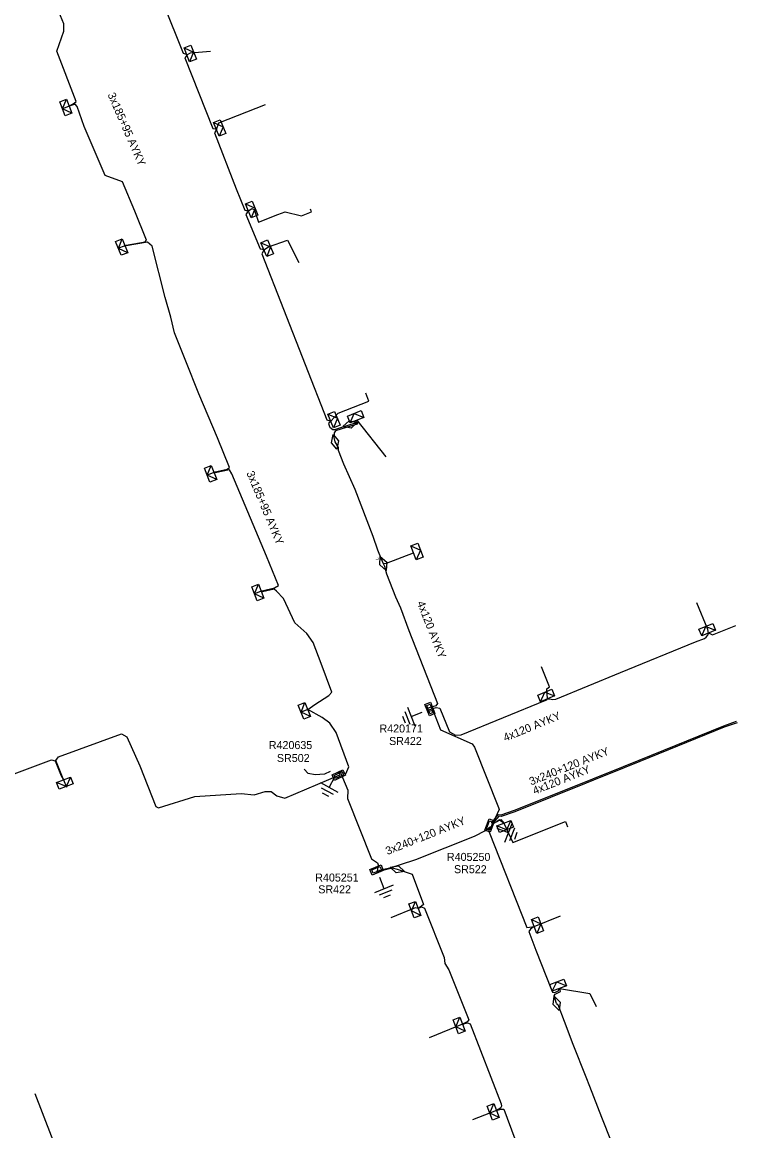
# Model space of a CAD drawing. Extents: x -540028 to -538776, y -1157064 to -1155670.
# Drawn here: x -539821.3 to -539732.2, y -1156179 to -1156040.4 of the extents above; entities that cross this region are included whole.
import ezdxf

# ---------------------------------------------------------------- set-up
doc = ezdxf.new("R2010")
doc.units = 0
for name, color, linetype in [('Vrstva 15', 7, 'Continuous'), ('Vrstva 19', 7, 'Continuous'), ('Vrstva 2', 7, 'Continuous'), ('Vrstva 28', 7, 'Continuous'), ('Vrstva 29', 7, 'Continuous'), ('Vrstva 30', 7, 'Continuous'), ('Vrstva 31', 7, 'Continuous'), ('Vrstva 5', 7, 'Continuous'), ('Vrstva 52', 7, 'Continuous'), ('Vrstva 59', 7, 'Continuous'), ('Vrstva 6', 7, 'Continuous')]:
    doc.layers.add(name, color=color, linetype=linetype)

# ---------------------------------------------------------------- blocks, each defined once
blk = doc.blocks.new('17')
at = {"layer": 'Vrstva 2'}
blk.add_lwpolyline([(-1.875, 0), (0, 0.9375), (1.875, 0), (0, -0.9375)], close=True, dxfattribs=at)
blk = doc.blocks.new('17.1')
at = {"layer": 'Vrstva 2'}
blk.add_lwpolyline([(-1.875, 0), (0, 0.9375), (1.875, 0), (0, -0.9375)], close=True, dxfattribs=at)
blk.add_text('T', height=0.75, dxfattribs=at).set_placement((-1.875, -1.35))
blk = doc.blocks.new('132')
at = {"layer": 'Vrstva 2'}
for points in [[(-1.5, 1.5), (1.5, 1.5), (1.5, 0), (-1.5, 0)], [(-1.1, 1.2), (1.1, 1.2), (1.1, 0.3), (-1.1, 0.3)]]:
    blk.add_lwpolyline(points, close=True, dxfattribs=at)
blk = doc.blocks.new('23')
at = {"layer": 'Vrstva 2'}
blk.add_lwpolyline([(1.875, -1.8), (-1.875, -1.8), (-1.875, 0), (1.875, 0)], close=True, dxfattribs=at)
blk.add_lwpolyline([(1.875, 0), (0, -1.8), (-1.875, 0)], dxfattribs=at)
blk = doc.blocks.new('11')
at = {"layer": 'Vrstva 2'}
for p, q in [((0, -4.3), (0, -1.3)), ((-2.5, -4.3), (2.5, -4.3)), ((-1.7, -5.3), (1.7, -5.3)), ((-0.9, -6.3), (0.9, -6.3))]:
    blk.add_line(p, q, dxfattribs=at)

msp = doc.modelspace()

# ---------------------------------------------------------------- linework, layer by layer
at = {"layer": 'Vrstva 5'}
for points in [[(-539781.35, -1156133.95), (-539781.26, -1156134.18), (-539780.81, -1156134.36), (-539780.46, -1156133.5), (-539782.03, -1156129.18), (-539782.81, -1156128.05), (-539783.79, -1156127.33), (-539785.58, -1156126.33), (-539784.69, -1156125.68), (-539782.94, -1156124.58), (-539782.58, -1156124.14), (-539783.91, -1156120.57), (-539784.89, -1156117.95), (-539785.71, -1156116.83), (-539787.18, -1156115.5), (-539788.62, -1156112.44), (-539789.5, -1156111.52), (-539789.77, -1156111.29), (-539791.22, -1156111.6), (-539791.41, -1156111.55), (-539791.28, -1156111.48), (-539789.71, -1156111.1), (-539789.24, -1156110.84), (-539790.75, -1156107.16), (-539795.07, -1156096.86), (-539795.36, -1156096.36), (-539797.14, -1156096.73), (-539797.3, -1156096.71), (-539797.16, -1156096.63), (-539795.66, -1156096.29), (-539795.36, -1156096.06), (-539796.86, -1156092.37), (-539799.2, -1156086.86), (-539800.81, -1156082.77), (-539802.21, -1156079.24), (-539802.67, -1156077.28), (-539803.41, -1156074.82), (-539805, -1156068.43), (-539805.6, -1156067.92), (-539808.26, -1156068.38), (-539808.41, -1156068.36), (-539808.27, -1156068.29), (-539805.91, -1156067.88), (-539805.72, -1156067.66), (-539807.17, -1156064.05), (-539808.72, -1156060.39), (-539810.88, -1156059.57), (-539813.54, -1156053.46), (-539814.41, -1156050.96), (-539814.63, -1156050.66), (-539815.25, -1156050.89), (-539815.39, -1156050.93), (-539815.27, -1156050.84), (-539814.76, -1156050.56), (-539814.54, -1156050.32), (-539816.94, -1156044.04), (-539816.06, -1156041.53), (-539816.06, -1156040.62), (-539818.34, -1156035.09)], [(-539803.6, -1156038.19), (-539801.16, -1156044.31), (-539800.79, -1156044.42), (-539800.68, -1156044.5), (-539800.72, -1156044.61), (-539800.94, -1156044.86), (-539797.44, -1156053.71), (-539797.13, -1156053.75), (-539797, -1156053.82), (-539797.03, -1156053.94), (-539797.24, -1156054.27), (-539794.53, -1156061.27), (-539793.43, -1156063.91), (-539793.24, -1156063.97), (-539793.11, -1156063.96), (-539792.99, -1156064.01), (-539793.01, -1156064.13), (-539793.14, -1156064.21), (-539793.32, -1156064.47), (-539791.53, -1156068.76), (-539791.2, -1156068.8), (-539791.07, -1156068.86), (-539791.09, -1156069), (-539791.3, -1156069.39), (-539783.2, -1156090.13), (-539782.94, -1156090.2), (-539782.82, -1156090.22), (-539782.71, -1156090.27), (-539782.74, -1156090.39), (-539782.9, -1156090.47), (-539783, -1156090.58), (-539782.85, -1156090.95), (-539782.82, -1156091.04), (-539782.44, -1156091.32), (-539782.2, -1156091.34), (-539780.29, -1156090.7)], [(-539780.29, -1156090.7), (-539779.56, -1156090.51), (-539779.52, -1156090.36), (-539779.42, -1156090.16), (-539779.31, -1156090.35), (-539779.4, -1156090.67), (-539780.23, -1156090.9), (-539782.09, -1156091.51), (-539782.29, -1156091.73), (-539782.31, -1156092.35), (-539782.17, -1156092.87)], [(-539782.17, -1156092.87), (-539781.78, -1156093.6), (-539781.78, -1156093.9), (-539781.11, -1156095.64), (-539779.67, -1156098.77), (-539777.43, -1156104.66), (-539776.87, -1156106.38), (-539776.39, -1156107.5), (-539776.14, -1156108.08)], [(-539776.14, -1156108.08), (-539775.99, -1156108.41), (-539775.75, -1156109.39), (-539774.61, -1156112.26), (-539773.97, -1156113.62), (-539772.96, -1156116.47), (-539769.37, -1156125.56), (-539769.57, -1156125.88), (-539770.7, -1156126.2)], [(-539770.62, -1156126.39), (-539769.51, -1156126.07), (-539769.08, -1156126.14), (-539767.84, -1156129.1), (-539767.11, -1156129.53), (-539766.39, -1156129.49), (-539755.82, -1156125.16), (-539755.7, -1156125.09), (-539755.6, -1156124.99), (-539755.38, -1156124.99), (-539754.95, -1156125.07), (-539754.56, -1156125.03), (-539746.48, -1156121.71), (-539737.12, -1156117.87), (-539735.98, -1156117.45), (-539735.78, -1156117.27), (-539735.59, -1156117.05), (-539735.54, -1156116.89), (-539735.47, -1156116.77), (-539735.34, -1156116.81), (-539734.99, -1156117.01), (-539732.06, -1156115.83)], [(-539770.55, -1156126.58), (-539770.09, -1156126.45), (-539769.85, -1156126.63), (-539768.97, -1156128.88), (-539765.04, -1156130.6), (-539764.75, -1156131.02), (-539761.72, -1156138.58), (-539761.66, -1156138.82), (-539762.15, -1156139.9), (-539762.49, -1156140.54), (-539762.46, -1156140.82), (-539762.44, -1156140.82)], [(-539762.42, -1156140.77), (-539762.58, -1156140.51), (-539761.77, -1156139.43), (-539761.41, -1156139.48), (-539759.74, -1156138.92), (-539750.84, -1156135.37), (-539749.03, -1156134.6), (-539748.05, -1156134.22), (-539744.15, -1156132.65), (-539733.59, -1156128.36), (-539731.98, -1156127.8)], [(-539731.92, -1156127.98), (-539733.53, -1156128.54), (-539744.07, -1156132.83), (-539747.97, -1156134.4), (-539748.95, -1156134.78), (-539750.76, -1156135.55), (-539759.68, -1156139.1), (-539761.39, -1156139.68), (-539761.69, -1156139.65), (-539762.44, -1156140.55), (-539762.39, -1156140.69)], [(-539825.3, -1156135.47), (-539817.59, -1156132.61), (-539817.16, -1156132.74), (-539816.41, -1156134.62), (-539816.11, -1156135.12), (-539816.31, -1156134.58), (-539817.07, -1156132.7), (-539816.73, -1156132.24), (-539808.85, -1156129.36), (-539808.2, -1156129.73), (-539806.58, -1156133.36), (-539804.55, -1156138.43), (-539804.22, -1156138.63), (-539799.69, -1156137.19), (-539793.91, -1156136.82), (-539792.27, -1156137), (-539790.9, -1156136.57), (-539790.16, -1156136.57), (-539789.43, -1156137.13), (-539788.43, -1156137.39), (-539781.58, -1156134.51), (-539781.74, -1156134.13)], [(-539781.55, -1156134.04), (-539780.56, -1156136.39), (-539780.62, -1156137.44), (-539777.61, -1156144.98), (-539776.86, -1156145.49), (-539776.76, -1156145.72), (-539776.93, -1156146.77)], [(-539762.45, -1156140.67), (-539762.94, -1156141.33), (-539762.91, -1156141.64), (-539758.18, -1156153.55), (-539757.85, -1156153.51), (-539757.29, -1156153.43), (-539757.72, -1156153.77), (-539757.93, -1156154.05), (-539757.05, -1156156.4), (-539755.72, -1156159.78), (-539755.19, -1156161.16), (-539754.98, -1156161.64), (-539754.69, -1156161.7), (-539754.2, -1156161.46), (-539754.21, -1156161.32), (-539754.13, -1156161.2)], [(-539762.48, -1156140.92), (-539762.5, -1156140.91), (-539762.45, -1156140.67)], [(-539762.45, -1156140.67), (-539762.42, -1156140.55), (-539761.92, -1156140.31)], [(-539761.92, -1156140.31), (-539762.37, -1156140.57), (-539762.45, -1156140.67)], [(-539761.59, -1156140.15), (-539761.61, -1156140.12), (-539761.92, -1156140.31)], [(-539761.92, -1156140.31), (-539761.59, -1156140.15)], [(-539761.59, -1156140.15), (-539761.45, -1156140.08), (-539761.07, -1156140.52), (-539761.59, -1156140.15)], [(-539776.83, -1156146.73), (-539776.57, -1156146.4), (-539775.01, -1156146.02), (-539773.98, -1156145.7), (-539772.06, -1156145.08), (-539764.72, -1156142.16), (-539763.35, -1156141.46), (-539762.79, -1156140.97), (-539762.51, -1156141.01)], [(-539776.68, -1156146.66), (-539776.54, -1156146.49), (-539775.02, -1156146.11), (-539774.39, -1156146.3)], [(-539774.39, -1156146.3), (-539772.51, -1156146.91), (-539771.12, -1156150.69), (-539771.36, -1156150.91), (-539771.78, -1156151.18), (-539771.34, -1156151), (-539770.97, -1156151.14), (-539768.51, -1156157.33), (-539768.45, -1156158.08), (-539767.94, -1156158.86), (-539765.43, -1156165.12), (-539765.64, -1156165.36), (-539766.23, -1156165.65), (-539765.6, -1156165.48), (-539765.28, -1156165.61), (-539761.4, -1156175.59), (-539761.34, -1156175.91), (-539761.47, -1156176.17), (-539761.97, -1156176.44), (-539761.43, -1156176.28), (-539761.06, -1156176.27), (-539759.68, -1156179.97)], [(-539754.47, -1156163.05), (-539754.79, -1156162.1), (-539754.65, -1156161.9), (-539753.98, -1156161.58), (-539754.02, -1156161.3), (-539754.13, -1156161.2)], [(-539754.47, -1156163.05), (-539754.32, -1156163.21), (-539753.53, -1156165.27), (-539752.45, -1156168.17), (-539750.8, -1156172.24), (-539750.34, -1156173.42), (-539748.88, -1156177.28), (-539747.67, -1156180.3), (-539747.55, -1156180.35), (-539747.29, -1156180.99)]]:
    msp.add_lwpolyline(points, dxfattribs=at)
at = {"layer": 'Vrstva 52'}
for points in [[(-539800.68, -1156044.5), (-539800.22, -1156044.27), (-539797.75, -1156044.03)], [(-539797, -1156053.82), (-539796.68, -1156053.02), (-539790.86, -1156050.71)], [(-539792.99, -1156064.01), (-539792.55, -1156063.72), (-539792.26, -1156063.84), (-539791.72, -1156065.42), (-539789.33, -1156064.48), (-539788.38, -1156064.14), (-539786.35, -1156064.63), (-539785.09, -1156064.14), (-539785.22, -1156063.81)], [(-539791.07, -1156068.86), (-539790.46, -1156068.52), (-539788.11, -1156067.68), (-539786.69, -1156070.45)], [(-539782.71, -1156090.27), (-539781.78, -1156089.28), (-539777.96, -1156087.78), (-539778.32, -1156086.81)], [(-539776.14, -1156108.08), (-539775.75, -1156108.03), (-539772.34, -1156106.75)], [(-539735.47, -1156116.77), (-539735.57, -1156116.33), (-539736.93, -1156112.99)], [(-539755.6, -1156124.99), (-539755.69, -1156123.75), (-539755.37, -1156123.51), (-539756.36, -1156121)], [(-539782.76, -1156134.07), (-539783.5, -1156134.4), (-539784.65, -1156134.49), (-539785.52, -1156134.33), (-539786.02, -1156133.77)], [(-539761.07, -1156140.52), (-539759.94, -1156142.95), (-539753.36, -1156140.34), (-539753.11, -1156140.98)], [(-539771.78, -1156151.18), (-539772.13, -1156151.13), (-539775.21, -1156152.37)], [(-539757.29, -1156153.43), (-539753.99, -1156152.13)], [(-539754.13, -1156161.2), (-539750.33, -1156161.83), (-539749.52, -1156163.45)], [(-539766.23, -1156165.65), (-539770.41, -1156167.37)], [(-539761.97, -1156176.44), (-539764.97, -1156177.61)]]:
    msp.add_lwpolyline(points, dxfattribs=at)
at = {"layer": 'Vrstva 59'}
for points in [[(-539815.39, -1156050.93), (-539816.32, -1156051.29)], [(-539808.41, -1156068.36), (-539809.34, -1156068.72)], [(-539779.42, -1156090.16), (-539775.8, -1156094.75)], [(-539797.3, -1156096.71), (-539798.23, -1156097.08)], [(-539791.41, -1156111.55), (-539792.33, -1156111.92)], [(-539785.58, -1156126.33), (-539786.51, -1156126.69)], [(-539816.11, -1156135.12), (-539815.74, -1156136.05)], [(-539801.29, -1156221.99), (-539819.63, -1156174.34)]]:
    msp.add_lwpolyline(points, dxfattribs=at)

# ---------------------------------------------------------------- block references
at = {"layer": 'Vrstva 15'}
for p, xscale, yscale, rotation in [((-539770.65, -1156126.4), 0.5, 0.5, -68.34053606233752), ((-539781.86, -1156134.19), 0.5000000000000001, 0.5, -28.96766117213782), ((-539762.49, -1156140.96), 0.49999999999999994, 0.5000000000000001, 68.96248884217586), ((-539776.83, -1156146.73), 0.5, 0.5, 22.14718609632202)]:
    msp.add_blockref('11', p, dxfattribs=dict(at, xscale=xscale, yscale=yscale, rotation=rotation))
at = {"layer": 'Vrstva 19', "yscale": 0.5}
for name, p, xscale, rotation in [('17', (-539780.29, -1156090.7), 0.5, 15.068488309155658), ('17', (-539782.17, -1156092.87), 0.49999999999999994, 105.06848819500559), ('17.1', (-539776.14, -1156108.08), 0.49999999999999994, -66.71813605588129), ('17', (-539774.39, -1156146.3), 0.5, -17.976591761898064), ('17', (-539754.47, -1156163.05), 0.49999999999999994, -71.38430834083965)]:
    msp.add_blockref(name, p, dxfattribs=dict(at, xscale=xscale, rotation=rotation))
at = {"layer": 'Vrstva 28'}
for p, xscale, yscale, rotation in [((-539770.65, -1156126.4), 0.5, 0.5, -68.52761672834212), ((-539781.86, -1156134.19), 0.5000000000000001, 0.5000000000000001, -154.7446638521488), ((-539762.49, -1156140.96), 0.49999999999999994, 0.5000000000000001, 68.96248884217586), ((-539776.83, -1156146.73), 0.5, 0.5, 22.14718609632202)]:
    msp.add_blockref('132', p, dxfattribs=dict(at, xscale=xscale, yscale=yscale, rotation=rotation))
at = {"layer": 'Vrstva 31'}
for p, xscale, yscale, rotation in [((-539800.68, -1156044.49), 0.5, 0.5000000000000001, 111.57325831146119), ((-539815.39, -1156050.92), 0.49999999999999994, 0.5, -68.4450194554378), ((-539796.99, -1156053.82), 0.5, 0.5, 111.77743053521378), ((-539792.99, -1156064.01), 0.5, 0.5000000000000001, 112.09416940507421), ((-539808.41, -1156068.36), 0.5, 0.5000000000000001, -68.44328604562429), ((-539791.07, -1156068.86), 0.5, 0.5, 112.95805287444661), ((-539782.71, -1156090.27), 0.5, 0.5, 111.83802224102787), ((-539779.42, -1156090.16), 0.49999999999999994, 0.5000000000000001, -158.16356870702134), ((-539797.3, -1156096.71), 0.49999999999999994, 0.5000000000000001, -68.4762361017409), ((-539772.34, -1156106.75), 0.5, 0.5, 110.97780271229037), ((-539791.4, -1156111.55), 0.5, 0.5, -68.38622222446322), ((-539735.47, -1156116.77), 0.5, 0.5, -157.49231676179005), ((-539755.6, -1156124.99), 0.49999999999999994, 0.5000000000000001, -157.63060270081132), ((-539785.58, -1156126.33), 0.5000000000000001, 0.5, -68.63264170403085), ((-539816.11, -1156135.12), 0.5000000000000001, 0.4999999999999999, 21.592372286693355), ((-539761.07, -1156140.52), 0.5, 0.5, 21.037511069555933), ((-539771.78, -1156151.18), 0.49999999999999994, 0.5000000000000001, -68.96248890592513), ((-539757.29, -1156153.43), 0.5, 0.5000000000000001, 111.03751110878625), ((-539754.13, -1156161.2), 0.5, 0.5, -159.9129499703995), ((-539766.23, -1156165.65), 0.49999999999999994, 0.5000000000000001, -68.96248889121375), ((-539761.97, -1156176.44), 0.49999999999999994, 0.5000000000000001, -68.96248884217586)]:
    msp.add_blockref('23', p, dxfattribs=dict(at, xscale=xscale, yscale=yscale, rotation=rotation))

# ---------------------------------------------------------------- texts
at = {"layer": 'Vrstva 29'}
for s, rotation, p in [('R420171', 0.048, (-539776.61, -1156129.2)), ('R420635', 0.005, (-539790.44, -1156131.27)), ('R405250', 359.852, (-539768.18, -1156145.24)), ('R405251', 0.081, (-539784.64, -1156147.83))]:
    msp.add_text(s, height=1, rotation=rotation, dxfattribs=at).set_placement(p)
at = {"layer": 'Vrstva 30'}
for s, rotation, p in [('SR422', 0.083, (-539775.41, -1156130.76)), ('SR502', 0.003, (-539789.43, -1156132.89)), ('SR522', 359.852, (-539767.3, -1156146.78)), ('SR422', 0.037, (-539784.26, -1156149.3))]:
    msp.add_text(s, height=1, rotation=rotation, dxfattribs=at).set_placement(p)
at = {"layer": 'Vrstva 6'}
for s, rotation, p in [('3x185+95 AYKY', 293.514, (-539810.62, -1156049.47)), ('3x185+95 AYKY', 292.757, (-539793.26, -1156096.76)), ('4x120 AYKY', 291.551, (-539771.95, -1156112.99)), ('4x120 AYKY', 22.276, (-539760.89, -1156130.35)), ('3x240+120 AYKY', 21.719, (-539757.66, -1156135.83)), ('4x120 AYKY', 21.728, (-539757.22, -1156136.98)), ('3x240+120 AYKY', 21.694, (-539775.61, -1156144.52))]:
    msp.add_text(s, height=1, rotation=rotation, dxfattribs=at).set_placement(p)

doc.saveas('drawing.dxf')
